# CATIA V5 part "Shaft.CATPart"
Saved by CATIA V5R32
Part number: Part2
Material "Iron": density 7870 kg/m3, Young's modulus 2.11e+11 Pa, Poisson ratio 0.291, thermal expansion 1.21e-05 1/K
Bounding box of the stored display mesh (mm): x -20.121 to 20.121, y 0 to 300, z -20.121 to 20.121
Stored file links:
  D:\PROJECTS\Project 2022\CATIA V5 6R 2022\Resources\Input file\c19_catia_v5_6r2022_inp\c19_catia_v5_6r2022_inp\c19_catia_v5_6r2022_inp\C19_tut_02.CATPart\Shaft.CATPart
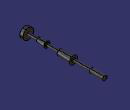
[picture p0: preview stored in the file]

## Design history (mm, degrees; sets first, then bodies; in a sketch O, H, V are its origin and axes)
Body1 (main body), material "Iron"
  Sketch1 on yz-plane, origin (0, 0, 0), H (0, 1, 0), V (0, 0, 1)
    line L1 (0, 0) -> (0, 20.127)
    line L2 (0, 20.127) -> (12.0221, 20.127)
    line L3 (12.0221, 20.127) -> (12.0221, 5.2746)
    point P3 (12.0221, 5.2746)
    line L4 (12.0221, 5.2746) -> (51.1457, 5.2746)
    line L5 (51.1457, 5.2746) -> (51.1457, 8.5349)
    line L6 (51.1457, 8.5349) -> (82.0221, 11.1079)
    line L7 (82.0221, 11.1079) -> (82.0221, 5.2746)
    point P7 (82.0221, 5.2746)
    line L8 (82.0221, 5.2746) -> (132.0221, 5.2746)
    line L9 (132.0221, 5.2746) -> (132.0221, 10.9839)
    line L10 (132.0221, 10.9839) -> (182.0221, 15.1506)
    line L11 (182.0221, 15.1506) -> (182.0221, 5.2746)
    point P11 (182.0221, 5.2746)
    line L12 (182.0221, 5.2746) -> (250, 5.2746)
    line L13 (250, 5.2746) -> (250, 8.5349)
    line L14 (250, 8.5349) -> (300, 8.5349)
    line L15 (300, 8.5349) -> (300, 0)
    point P15 (300, 0)
    axis line L16 (0, 0) -> (300, 0)
    distance L15 L1 = 300
    distance L13 L1 = 250
    distance L11 L7 = 100
    distance L3 L7 = 70
    distance L9 L11 = 50
    vertical: L1 V, L3 V, L5 V, L7 V, L9 V, L11 V, L13 V, L15 V
    horizontal: L2 H, L4 H, L8 H, L12 H, L14 H, L16 H
    coincidence: L6 P3, P7 L4, P11 L4, P15 H
    parallelism: L10 L6
  Shaft1: profile Sketch1, axis Sketch1.L16, angle 360
  Fillet1: radius 2, on edge [face of Shaft1 from Sketch1.L7 | face of Shaft1 from Sketch1.L8]; edge [face of Shaft1 from Sketch1.L4 | face of Shaft1 from Sketch1.L5]; edge [face of Shaft1 from Sketch1.L8 | face of Shaft1 from Sketch1.L9]; edge [face of Shaft1 from Sketch1.L11 | face of Shaft1 from Sketch1.L12]; edge [face of Shaft1 from Sketch1.L12 | face of Shaft1 from Sketch1.L13]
